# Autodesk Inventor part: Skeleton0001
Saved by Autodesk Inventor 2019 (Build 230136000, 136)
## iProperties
_SkeletonDoc: Frame Skeleton File
_Version: 15.0.0
Created: 2018-07
Part Number: Skeleton0001
Material: Générique
Document SubType Name: Modeling
Designer: Fabian Perrée
Density: 1 g/cm^3
Appearance: Par défaut
Author: Fabian Perrée
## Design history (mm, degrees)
sketch "Squelette de référence"
